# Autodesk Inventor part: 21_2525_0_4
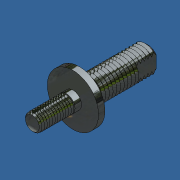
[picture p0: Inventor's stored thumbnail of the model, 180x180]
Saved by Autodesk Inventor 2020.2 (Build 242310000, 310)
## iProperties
Part Number: 21_2525_0_4
Material: Steel
Document SubType Name: Modeling
Designer: amoles
Appearance: Zinc
Mass: 39.5721 g
Surface Area: 33.6447 cm^2
Volume: 5.04103 cm^3
Density: 7.85 g/cm^3
Author: amoles
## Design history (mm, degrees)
feature "Base1"
body "Solid1"
